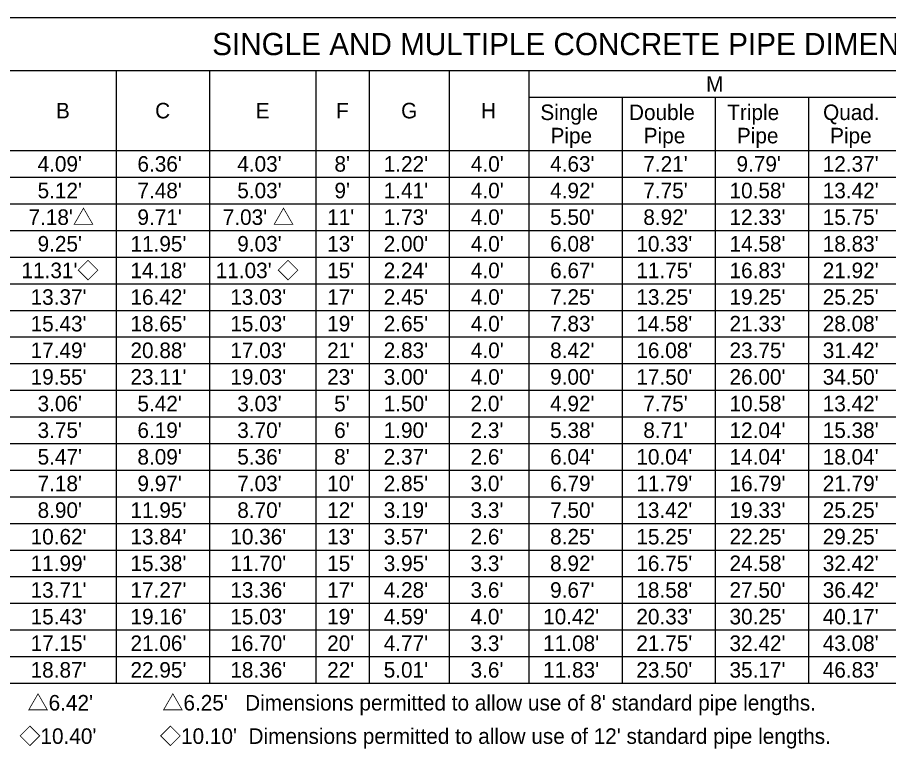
# Model space of a CAD drawing. Extents: x -1.3 to 14.5, y 0 to 8.2.
# Drawn here: x 4.015 to 7.941, y 4.933 to 8.227 of the extents above; entities that cross this region are included whole.
import ezdxf

# ---------------------------------------------------------------- set-up
doc = ezdxf.new("R2010")
doc.units = 0
doc.layers.add('TextNotes', color=7, linetype='Continuous')
doc.layers.add('TextTables', color=7, linetype='Continuous')

msp = doc.modelspace()

# ---------------------------------------------------------------- linework, layer by layer
at = {"layer": 'TextTables'}
msp.add_line((2, 8.2274), (13.4, 8.2274), dxfattribs=at)
for points in [[(13.4, 7.9874), (11.72, 7.9874), (10.04, 7.9874), (8.36, 7.9874), (8, 7.9874), (6.32, 7.9874), (5.96, 7.9874), (5.6, 7.9874), (5.36, 7.9874), (4.88, 7.9874), (4.46, 7.9874), (3.98, 7.9874), (3.56, 7.9874), (3.14, 7.9874), (2.84, 7.9874), (2.54, 7.9874), (2.24, 7.9874), (2, 7.9874)], [(4.46, 7.9874), (4.46, 7.6274), (4.46, 7.5074), (4.46, 7.3874), (4.46, 7.2674), (4.46, 7.1474), (4.46, 7.0274), (4.46, 6.9074), (4.46, 6.7874), (4.46, 6.6674), (4.46, 6.5474), (4.46, 6.4274), (4.46, 6.3074), (4.46, 6.1874), (4.46, 6.0674), (4.46, 5.9474), (4.46, 5.8274), (4.46, 5.7074), (4.46, 5.5874), (4.46, 5.4674), (4.46, 5.3474), (4.46, 5.2274)], [(4.88, 7.9874), (4.88, 7.6274), (4.88, 7.5074), (4.88, 7.3874), (4.88, 7.2674), (4.88, 7.1474), (4.88, 7.0274), (4.88, 6.9074), (4.88, 6.7874), (4.88, 6.6674), (4.88, 6.5474), (4.88, 6.4274), (4.88, 6.3074), (4.88, 6.1874), (4.88, 6.0674), (4.88, 5.9474), (4.88, 5.8274), (4.88, 5.7074), (4.88, 5.5874), (4.88, 5.4674), (4.88, 5.3474), (4.88, 5.2274)], [(5.36, 7.9874), (5.36, 7.6274), (5.36, 7.5074), (5.36, 7.3874), (5.36, 7.2674), (5.36, 7.1474), (5.36, 7.0274), (5.36, 6.9074), (5.36, 6.7874), (5.36, 6.6674), (5.36, 6.5474), (5.36, 6.4274), (5.36, 6.3074), (5.36, 6.1874), (5.36, 6.0674), (5.36, 5.9474), (5.36, 5.8274), (5.36, 5.7074), (5.36, 5.5874), (5.36, 5.4674), (5.36, 5.3474), (5.36, 5.2274)], [(5.6, 7.9874), (5.6, 7.6274), (5.6, 7.5074), (5.6, 7.3874), (5.6, 7.2674), (5.6, 7.1474), (5.6, 7.0274), (5.6, 6.9074), (5.6, 6.7874), (5.6, 6.6674), (5.6, 6.5474), (5.6, 6.4274), (5.6, 6.3074), (5.6, 6.1874), (5.6, 6.0674), (5.6, 5.9474), (5.6, 5.8274), (5.6, 5.7074), (5.6, 5.5874), (5.6, 5.4674), (5.6, 5.3474), (5.6, 5.2274)], [(5.96, 7.9874), (5.96, 7.6274), (5.96, 7.5074), (5.96, 7.3874), (5.96, 7.2674), (5.96, 7.1474), (5.96, 7.0274), (5.96, 6.9074), (5.96, 6.7874), (5.96, 6.6674), (5.96, 6.5474), (5.96, 6.4274), (5.96, 6.3074), (5.96, 6.1874), (5.96, 6.0674), (5.96, 5.9474), (5.96, 5.8274), (5.96, 5.7074), (5.96, 5.5874), (5.96, 5.4674), (5.96, 5.3474), (5.96, 5.2274)], [(6.32, 7.9874), (6.32, 7.8674), (6.32, 7.6274), (6.32, 7.5074), (6.32, 7.3874), (6.32, 7.2674), (6.32, 7.1474), (6.32, 7.0274), (6.32, 6.9074), (6.32, 6.7874), (6.32, 6.6674), (6.32, 6.5474), (6.32, 6.4274), (6.32, 6.3074), (6.32, 6.1874), (6.32, 6.0674), (6.32, 5.9474), (6.32, 5.8274), (6.32, 5.7074), (6.32, 5.5874), (6.32, 5.4674), (6.32, 5.3474), (6.32, 5.2274)], [(6.32, 7.8674), (6.74, 7.8674), (7.16, 7.8674), (7.58, 7.8674), (8, 7.8674)], [(6.74, 7.8674), (6.74, 7.6274), (6.74, 7.5074), (6.74, 7.3874), (6.74, 7.2674), (6.74, 7.1474), (6.74, 7.0274), (6.74, 6.9074), (6.74, 6.7874), (6.74, 6.6674), (6.74, 6.5474), (6.74, 6.4274), (6.74, 6.3074), (6.74, 6.1874), (6.74, 6.0674), (6.74, 5.9474), (6.74, 5.8274), (6.74, 5.7074), (6.74, 5.5874), (6.74, 5.4674), (6.74, 5.3474), (6.74, 5.2274)], [(7.16, 7.8674), (7.16, 7.6274), (7.16, 7.5074), (7.16, 7.3874), (7.16, 7.2674), (7.16, 7.1474), (7.16, 7.0274), (7.16, 6.9074), (7.16, 6.7874), (7.16, 6.6674), (7.16, 6.5474), (7.16, 6.4274), (7.16, 6.3074), (7.16, 6.1874), (7.16, 6.0674), (7.16, 5.9474), (7.16, 5.8274), (7.16, 5.7074), (7.16, 5.5874), (7.16, 5.4674), (7.16, 5.3474), (7.16, 5.2274)], [(7.58, 7.8674), (7.58, 7.6274), (7.58, 7.5074), (7.58, 7.3874), (7.58, 7.2674), (7.58, 7.1474), (7.58, 7.0274), (7.58, 6.9074), (7.58, 6.7874), (7.58, 6.6674), (7.58, 6.5474), (7.58, 6.4274), (7.58, 6.3074), (7.58, 6.1874), (7.58, 6.0674), (7.58, 5.9474), (7.58, 5.8274), (7.58, 5.7074), (7.58, 5.5874), (7.58, 5.4674), (7.58, 5.3474), (7.58, 5.2274)], [(3.98, 7.6274), (4.46, 7.6274), (4.88, 7.6274), (5.36, 7.6274), (5.6, 7.6274), (5.96, 7.6274), (6.32, 7.6274), (6.74, 7.6274), (7.16, 7.6274), (7.58, 7.6274), (8, 7.6274), (8.36, 7.6274), (9.2, 7.6274), (10.04, 7.6274), (10.46, 7.6274), (10.88, 7.6274), (11.3, 7.6274), (11.72, 7.6274), (12.14, 7.6274), (12.56, 7.6274), (12.98, 7.6274), (13.4, 7.6274)], [(3.98, 7.5074), (4.46, 7.5074), (4.88, 7.5074), (5.36, 7.5074), (5.6, 7.5074), (5.96, 7.5074), (6.32, 7.5074), (6.74, 7.5074), (7.16, 7.5074), (7.58, 7.5074), (8, 7.5074), (8.36, 7.5074), (9.2, 7.5074), (10.04, 7.5074), (10.46, 7.5074), (10.88, 7.5074), (11.3, 7.5074), (11.72, 7.5074), (12.14, 7.5074), (12.56, 7.5074), (12.98, 7.5074), (13.4, 7.5074)], [(3.98, 7.3874), (4.46, 7.3874), (4.88, 7.3874), (5.36, 7.3874), (5.6, 7.3874), (5.96, 7.3874), (6.32, 7.3874), (6.74, 7.3874), (7.16, 7.3874), (7.58, 7.3874), (8, 7.3874), (8.36, 7.3874), (9.2, 7.3874), (10.04, 7.3874), (10.46, 7.3874), (10.88, 7.3874), (11.3, 7.3874), (11.72, 7.3874), (12.14, 7.3874), (12.56, 7.3874), (12.98, 7.3874), (13.4, 7.3874)], [(3.98, 7.2674), (4.46, 7.2674), (4.88, 7.2674), (5.36, 7.2674), (5.6, 7.2674), (5.96, 7.2674), (6.32, 7.2674), (6.74, 7.2674), (7.16, 7.2674), (7.58, 7.2674), (8, 7.2674), (8.36, 7.2674), (9.2, 7.2674), (10.04, 7.2674), (10.46, 7.2674), (10.88, 7.2674), (11.3, 7.2674), (11.72, 7.2674), (12.14, 7.2674), (12.56, 7.2674), (12.98, 7.2674), (13.4, 7.2674)], [(3.98, 7.1474), (4.46, 7.1474), (4.88, 7.1474), (5.36, 7.1474), (5.6, 7.1474), (5.96, 7.1474), (6.32, 7.1474), (6.74, 7.1474), (7.16, 7.1474), (7.58, 7.1474), (8, 7.1474), (8.36, 7.1474), (9.2, 7.1474), (10.04, 7.1474), (10.46, 7.1474), (10.88, 7.1474), (11.3, 7.1474), (11.72, 7.1474), (12.14, 7.1474), (12.56, 7.1474), (12.98, 7.1474), (13.4, 7.1474)], [(3.98, 7.0274), (4.46, 7.0274), (4.88, 7.0274), (5.36, 7.0274), (5.6, 7.0274), (5.96, 7.0274), (6.32, 7.0274), (6.74, 7.0274), (7.16, 7.0274), (7.58, 7.0274), (8, 7.0274), (8.36, 7.0274), (9.2, 7.0274), (10.04, 7.0274), (10.46, 7.0274), (10.88, 7.0274), (11.3, 7.0274), (11.72, 7.0274), (12.14, 7.0274), (12.56, 7.0274), (12.98, 7.0274), (13.4, 7.0274)], [(3.98, 6.9074), (4.46, 6.9074), (4.88, 6.9074), (5.36, 6.9074), (5.6, 6.9074), (5.96, 6.9074), (6.32, 6.9074), (6.74, 6.9074), (7.16, 6.9074), (7.58, 6.9074), (8, 6.9074), (8.36, 6.9074), (9.2, 6.9074), (10.04, 6.9074), (10.46, 6.9074), (10.88, 6.9074), (11.3, 6.9074), (11.72, 6.9074), (12.14, 6.9074), (12.56, 6.9074), (12.98, 6.9074), (13.4, 6.9074)], [(3.98, 6.7874), (4.46, 6.7874), (4.88, 6.7874), (5.36, 6.7874), (5.6, 6.7874), (5.96, 6.7874), (6.32, 6.7874), (6.74, 6.7874), (7.16, 6.7874), (7.58, 6.7874), (8, 6.7874), (8.36, 6.7874), (9.2, 6.7874), (10.04, 6.7874), (10.46, 6.7874), (10.88, 6.7874), (11.3, 6.7874), (11.72, 6.7874), (12.14, 6.7874), (12.56, 6.7874), (12.98, 6.7874), (13.4, 6.7874)], [(3.98, 6.6674), (4.46, 6.6674), (4.88, 6.6674), (5.36, 6.6674), (5.6, 6.6674), (5.96, 6.6674), (6.32, 6.6674), (6.74, 6.6674), (7.16, 6.6674), (7.58, 6.6674), (8, 6.6674), (8.36, 6.6674), (9.2, 6.6674), (10.04, 6.6674), (10.46, 6.6674), (10.88, 6.6674), (11.3, 6.6674), (11.72, 6.6674), (12.14, 6.6674), (12.56, 6.6674), (12.98, 6.6674), (13.4, 6.6674)], [(3.98, 6.5474), (4.46, 6.5474), (4.88, 6.5474), (5.36, 6.5474), (5.6, 6.5474), (5.96, 6.5474), (6.32, 6.5474), (6.74, 6.5474), (7.16, 6.5474), (7.58, 6.5474), (8, 6.5474), (8.36, 6.5474), (9.2, 6.5474), (10.04, 6.5474), (10.46, 6.5474), (10.88, 6.5474), (11.3, 6.5474), (11.72, 6.5474), (12.14, 6.5474), (12.56, 6.5474), (12.98, 6.5474), (13.4, 6.5474)], [(3.98, 6.4274), (4.46, 6.4274), (4.88, 6.4274), (5.36, 6.4274), (5.6, 6.4274), (5.96, 6.4274), (6.32, 6.4274), (6.74, 6.4274), (7.16, 6.4274), (7.58, 6.4274), (8, 6.4274), (8.36, 6.4274), (9.2, 6.4274), (10.04, 6.4274), (10.46, 6.4274), (10.88, 6.4274), (11.3, 6.4274), (11.72, 6.4274), (12.14, 6.4274), (12.56, 6.4274), (12.98, 6.4274), (13.4, 6.4274)], [(3.98, 6.3074), (4.46, 6.3074), (4.88, 6.3074), (5.36, 6.3074), (5.6, 6.3074), (5.96, 6.3074), (6.32, 6.3074), (6.74, 6.3074), (7.16, 6.3074), (7.58, 6.3074), (8, 6.3074), (8.36, 6.3074), (9.2, 6.3074), (10.04, 6.3074), (10.46, 6.3074), (10.88, 6.3074), (11.3, 6.3074), (11.72, 6.3074), (12.14, 6.3074), (12.56, 6.3074), (12.98, 6.3074), (13.4, 6.3074)], [(3.98, 6.1874), (4.46, 6.1874), (4.88, 6.1874), (5.36, 6.1874), (5.6, 6.1874), (5.96, 6.1874), (6.32, 6.1874), (6.74, 6.1874), (7.16, 6.1874), (7.58, 6.1874), (8, 6.1874), (8.36, 6.1874), (9.2, 6.1874), (10.04, 6.1874), (10.46, 6.1874), (10.88, 6.1874), (11.3, 6.1874), (11.72, 6.1874), (12.14, 6.1874), (12.56, 6.1874), (12.98, 6.1874), (13.4, 6.1874)], [(3.98, 6.0674), (4.46, 6.0674), (4.88, 6.0674), (5.36, 6.0674), (5.6, 6.0674), (5.96, 6.0674), (6.32, 6.0674), (6.74, 6.0674), (7.16, 6.0674), (7.58, 6.0674), (8, 6.0674), (8.36, 6.0674), (9.2, 6.0674), (10.04, 6.0674), (10.46, 6.0674), (10.88, 6.0674), (11.3, 6.0674), (11.72, 6.0674), (12.14, 6.0674), (12.56, 6.0674), (12.98, 6.0674), (13.4, 6.0674)], [(3.98, 5.9474), (4.46, 5.9474), (4.88, 5.9474), (5.36, 5.9474), (5.6, 5.9474), (5.96, 5.9474), (6.32, 5.9474), (6.74, 5.9474), (7.16, 5.9474), (7.58, 5.9474), (8, 5.9474), (8.36, 5.9474), (9.2, 5.9474), (10.04, 5.9474), (10.46, 5.9474), (10.88, 5.9474), (11.3, 5.9474), (11.72, 5.9474), (12.14, 5.9474), (12.56, 5.9474), (12.98, 5.9474), (13.4, 5.9474)], [(3.98, 5.8274), (4.46, 5.8274), (4.88, 5.8274), (5.36, 5.8274), (5.6, 5.8274), (5.96, 5.8274), (6.32, 5.8274), (6.74, 5.8274), (7.16, 5.8274), (7.58, 5.8274), (8, 5.8274), (8.36, 5.8274), (9.2, 5.8274), (10.04, 5.8274), (10.46, 5.8274), (10.88, 5.8274), (11.3, 5.8274), (11.72, 5.8274), (12.14, 5.8274), (12.56, 5.8274), (12.98, 5.8274), (13.4, 5.8274)], [(3.98, 5.7074), (4.46, 5.7074), (4.88, 5.7074), (5.36, 5.7074), (5.6, 5.7074), (5.96, 5.7074), (6.32, 5.7074), (6.74, 5.7074), (7.16, 5.7074), (7.58, 5.7074), (8, 5.7074), (8.36, 5.7074), (9.2, 5.7074), (10.04, 5.7074), (10.46, 5.7074), (10.88, 5.7074), (11.3, 5.7074), (11.72, 5.7074), (12.14, 5.7074), (12.56, 5.7074), (12.98, 5.7074), (13.4, 5.7074)], [(3.98, 5.5874), (4.46, 5.5874), (4.88, 5.5874), (5.36, 5.5874), (5.6, 5.5874), (5.96, 5.5874), (6.32, 5.5874), (6.74, 5.5874), (7.16, 5.5874), (7.58, 5.5874), (8, 5.5874), (8.36, 5.5874), (9.2, 5.5874), (10.04, 5.5874), (10.46, 5.5874), (10.88, 5.5874), (11.3, 5.5874), (11.72, 5.5874), (12.14, 5.5874), (12.56, 5.5874), (12.98, 5.5874), (13.4, 5.5874)], [(3.98, 5.4674), (4.46, 5.4674), (4.88, 5.4674), (5.36, 5.4674), (5.6, 5.4674), (5.96, 5.4674), (6.32, 5.4674), (6.74, 5.4674), (7.16, 5.4674), (7.58, 5.4674), (8, 5.4674), (8.36, 5.4674), (9.2, 5.4674), (10.04, 5.4674), (10.46, 5.4674), (10.88, 5.4674), (11.3, 5.4674), (11.72, 5.4674), (12.14, 5.4674), (12.56, 5.4674), (12.98, 5.4674), (13.4, 5.4674)], [(3.98, 5.3474), (4.46, 5.3474), (4.88, 5.3474), (5.36, 5.3474), (5.6, 5.3474), (5.96, 5.3474), (6.32, 5.3474), (6.74, 5.3474), (7.16, 5.3474), (7.58, 5.3474), (8, 5.3474), (8.36, 5.3474), (9.2, 5.3474), (10.04, 5.3474), (10.46, 5.3474), (10.88, 5.3474), (11.3, 5.3474), (11.72, 5.3474), (12.14, 5.3474), (12.56, 5.3474), (12.98, 5.3474), (13.4, 5.3474)], [(3.98, 5.2274), (4.46, 5.2274), (4.88, 5.2274), (5.36, 5.2274), (5.6, 5.2274), (5.96, 5.2274), (6.32, 5.2274), (6.74, 5.2274), (7.16, 5.2274), (7.58, 5.2274), (8, 5.2274), (8.36, 5.2274), (8.78, 5.2274), (9.2, 5.2274), (9.62, 5.2274), (10.04, 5.2274), (10.46, 5.2274), (10.88, 5.2274), (11.3, 5.2274), (11.72, 5.2274), (12.14, 5.2274), (12.56, 5.2274), (12.98, 5.2274), (13.4, 5.2274)]]:
    msp.add_lwpolyline(points, dxfattribs=at)

# ---------------------------------------------------------------- texts
at = {"layer": 'TextNotes'}
for s, height, p in [('SINGLE AND MULTIPLE CONCRETE PIPE DIMENSIONS AND QUANTITIES', 0.1, (4.8923, 8.0574)), ('M', 0.07, (7.1183, 7.8924)), ('B', 0.07, (4.1883, 7.7724)), ('C', 0.07, (4.6352, 7.7724)), ('E', 0.07, (5.0882, 7.7724)), ('F', 0.07, (5.4503, 7.7724)), ('G', 0.07, (5.7438, 7.7724)), ('H', 0.07, (6.1037, 7.7724)), ('Single', 0.07, (6.3714, 7.7649)), ('Double', 0.07, (6.7709, 7.7649)), ('Triple', 0.07, (7.2137, 7.7649)), ('Quad.', 0.07, (7.6457, 7.7649)), ('Pipe', 0.07, (6.4173, 7.6599)), ('Pipe', 0.07, (6.8373, 7.6599)), ('Pipe', 0.07, (7.2573, 7.6599)), ('Pipe', 0.07, (7.6773, 7.6599))]:
    msp.add_text(s, height=height, dxfattribs=at).set_placement(p)
for s, p in [("4.09'", (4.1054, 7.5324)), ("6.36'", (4.5554, 7.5324)), ("4.03'", (5.0054, 7.5324)), (" 8'", (5.4175, 7.5324)), ("1.22'", (5.6654, 7.5324)), (" 4.0'", (6.0323, 7.5324)), ("4.63'", (6.4154, 7.5324)), ("7.21'", (6.8354, 7.5324)), ("9.79'", (7.2554, 7.5324)), ("12.37'", (7.644, 7.5324)), ("5.12'", (4.1054, 7.4124)), ("7.48'", (4.5554, 7.4124)), ("5.03'", (5.0054, 7.4124)), (" 9'", (5.4175, 7.4124)), ("1.41'", (5.6654, 7.4124)), (" 4.0'", (6.0323, 7.4124)), ("4.92'", (6.4154, 7.4124)), ("7.75'", (6.8354, 7.4124)), ("10.58'", (7.224, 7.4124)), ("13.42'", (7.644, 7.4124)), ("7.18'△", (4.0645, 7.2924)), ("9.71'", (4.5554, 7.2924)), ("7.03' △", (4.94, 7.2924)), ("11'", (5.4106, 7.2924)), ("1.73'", (5.6654, 7.2924)), (" 4.0'", (6.0323, 7.2924)), ("5.50'", (6.4154, 7.2924)), ("8.92'", (6.8354, 7.2924)), ("12.33'", (7.224, 7.2924)), ("15.75'", (7.644, 7.2924)), ("9.25'", (4.1054, 7.1724)), ("11.95'", (4.524, 7.1724)), ("9.03'", (5.0054, 7.1724)), ("13'", (5.4106, 7.1724)), ("2.00'", (5.6654, 7.1724)), (" 4.0'", (6.0323, 7.1724)), ("6.08'", (6.4154, 7.1724)), ("10.33'", (6.804, 7.1724)), ("14.58'", (7.224, 7.1724)), ("18.83'", (7.644, 7.1724)), ("11.31'◇", (4.0329, 7.0524)), ("14.18'", (4.524, 7.0524)), ("11.03' ◇", (4.9083, 7.0524)), ("15'", (5.4106, 7.0524)), ("2.24'", (5.6654, 7.0524)), (" 4.0'", (6.0323, 7.0524)), ("6.67'", (6.4154, 7.0524)), ("11.75'", (6.804, 7.0524)), ("16.83'", (7.224, 7.0524)), ("21.92'", (7.644, 7.0524)), ("13.37'", (4.074, 6.9324)), ("16.42'", (4.524, 6.9324)), ("13.03'", (4.974, 6.9324)), ("17'", (5.4106, 6.9324)), ("2.45'", (5.6654, 6.9324)), (" 4.0'", (6.0323, 6.9324)), ("7.25'", (6.4154, 6.9324)), ("13.25'", (6.804, 6.9324)), ("19.25'", (7.224, 6.9324)), ("25.25'", (7.644, 6.9324)), ("15.43'", (4.074, 6.8124)), ("18.65'", (4.524, 6.8124)), ("15.03'", (4.974, 6.8124)), ("19'", (5.4106, 6.8124)), ("2.65'", (5.6654, 6.8124)), (" 4.0'", (6.0323, 6.8124)), ("7.83'", (6.4154, 6.8124)), ("14.58'", (6.804, 6.8124)), ("21.33'", (7.224, 6.8124)), ("28.08'", (7.644, 6.8124)), ("17.49'", (4.074, 6.6924)), ("20.88'", (4.524, 6.6924)), ("17.03'", (4.974, 6.6924)), ("21'", (5.4106, 6.6924)), ("2.83'", (5.6654, 6.6924)), (" 4.0'", (6.0323, 6.6924)), ("8.42'", (6.4154, 6.6924)), ("16.08'", (6.804, 6.6924)), ("23.75'", (7.224, 6.6924)), ("31.42'", (7.644, 6.6924)), ("19.55'", (4.074, 6.5724)), ("23.11'", (4.524, 6.5724)), ("19.03'", (4.974, 6.5724)), ("23'", (5.4106, 6.5724)), ("3.00'", (5.6654, 6.5724)), (" 4.0'", (6.0323, 6.5724)), ("9.00'", (6.4154, 6.5724)), ("17.50'", (6.804, 6.5724)), ("26.00'", (7.224, 6.5724)), ("34.50'", (7.644, 6.5724)), ("3.06'", (4.1054, 6.4524)), ("5.42'", (4.5554, 6.4524)), ("3.03'", (5.0054, 6.4524)), ("5'", (5.4421, 6.4524)), ("1.50'", (5.6654, 6.4524)), ("2.0'", (6.0569, 6.4524)), ("4.92'", (6.4154, 6.4524)), ("7.75'", (6.8354, 6.4524)), ("10.58'", (7.224, 6.4524)), ("13.42'", (7.644, 6.4524)), ("3.75'", (4.1054, 6.3324)), ("6.19'", (4.5554, 6.3324)), ("3.70'", (5.0054, 6.3324)), ("6'", (5.4421, 6.3324)), ("1.90'", (5.6654, 6.3324)), ("2.3'", (6.0569, 6.3324)), ("5.38'", (6.4154, 6.3324)), ("8.71'", (6.8354, 6.3324)), ("12.04'", (7.224, 6.3324)), ("15.38'", (7.644, 6.3324)), ("5.47'", (4.1054, 6.2124)), ("8.09'", (4.5554, 6.2124)), ("5.36'", (5.0054, 6.2124)), ("8'", (5.4421, 6.2124)), ("2.37'", (5.6654, 6.2124)), ("2.6'", (6.0569, 6.2124)), ("6.04'", (6.4154, 6.2124)), ("10.04'", (6.804, 6.2124)), ("14.04'", (7.224, 6.2124)), ("18.04'", (7.644, 6.2124)), ("7.18'", (4.1054, 6.0924)), ("9.97'", (4.5554, 6.0924)), ("7.03'", (5.0054, 6.0924)), ("10'", (5.4106, 6.0924)), ("2.85'", (5.6654, 6.0924)), ("3.0'", (6.0569, 6.0924)), ("6.79'", (6.4154, 6.0924)), ("11.79'", (6.804, 6.0924)), ("16.79'", (7.224, 6.0924)), ("21.79'", (7.644, 6.0924)), ("8.90'", (4.1054, 5.9724)), ("11.95'", (4.524, 5.9724)), ("8.70'", (5.0054, 5.9724)), ("12'", (5.4106, 5.9724)), ("3.19'", (5.6654, 5.9724)), ("3.3'", (6.0569, 5.9724)), ("7.50'", (6.4154, 5.9724)), ("13.42'", (6.804, 5.9724)), ("19.33'", (7.224, 5.9724)), ("25.25'", (7.644, 5.9724)), ("10.62'", (4.074, 5.8524)), ("13.84'", (4.524, 5.8524)), ("10.36'", (4.974, 5.8524)), ("13'", (5.4106, 5.8524)), ("3.57'", (5.6654, 5.8524)), ("2.6'", (6.0569, 5.8524)), ("8.25'", (6.4154, 5.8524)), ("15.25'", (6.804, 5.8524)), ("22.25'", (7.224, 5.8524)), ("29.25'", (7.644, 5.8524)), ("11.99'", (4.074, 5.7324)), ("15.38'", (4.524, 5.7324)), ("11.70'", (4.974, 5.7324)), ("15'", (5.4106, 5.7324)), ("3.95'", (5.6654, 5.7324)), ("3.3'", (6.0569, 5.7324)), ("8.92'", (6.4154, 5.7324)), ("16.75'", (6.804, 5.7324)), ("24.58'", (7.224, 5.7324)), ("32.42'", (7.644, 5.7324)), ("13.71'", (4.074, 5.6124)), ("17.27'", (4.524, 5.6124)), ("13.36'", (4.974, 5.6124)), ("17'", (5.4106, 5.6124)), ("4.28'", (5.6654, 5.6124)), ("3.6'", (6.0569, 5.6124)), ("9.67'", (6.4154, 5.6124)), ("18.58'", (6.804, 5.6124)), ("27.50'", (7.224, 5.6124)), ("36.42'", (7.644, 5.6124)), ("15.43'", (4.074, 5.4924)), ("19.16'", (4.524, 5.4924)), ("15.03'", (4.974, 5.4924)), ("19'", (5.4106, 5.4924)), ("4.59'", (5.6654, 5.4924)), ("4.0'", (6.0569, 5.4924)), ("10.42'", (6.384, 5.4924)), ("20.33'", (6.804, 5.4924)), ("30.25'", (7.224, 5.4924)), ("40.17'", (7.644, 5.4924)), ("17.15'", (4.074, 5.3724)), ("21.06'", (4.524, 5.3724)), ("16.70'", (4.974, 5.3724)), ("20'", (5.4106, 5.3724)), ("4.77'", (5.6654, 5.3724)), ("3.3'", (6.0569, 5.3724)), ("11.08'", (6.384, 5.3724)), ("21.75'", (6.804, 5.3724)), ("32.42'", (7.224, 5.3724)), ("43.08'", (7.644, 5.3724)), ("18.87'", (4.074, 5.2524)), ("22.95'", (4.524, 5.2524)), ("18.36'", (4.974, 5.2524)), ("22'", (5.4106, 5.2524)), ("5.01'", (5.6654, 5.2524)), ("3.6'", (6.0569, 5.2524)), ("11.83'", (6.384, 5.2524)), ("23.50'", (6.804, 5.2524)), ("35.17'", (7.224, 5.2524)), ("46.83'", (7.644, 5.2524)), ("△6.42'            △6.25'   Dimensions permitted to allow use of 8' standard pipe lengths.", (4.0597, 5.1042)), ("◇10.40'           ◇10.10'  Dimensions permitted to allow use of 12' standard pipe lengths.", (4.0228, 4.9539))]:
    msp.add_text(s, height=0.07, rotation=0, dxfattribs=at).set_placement(p)

doc.saveas('drawing.dxf')
